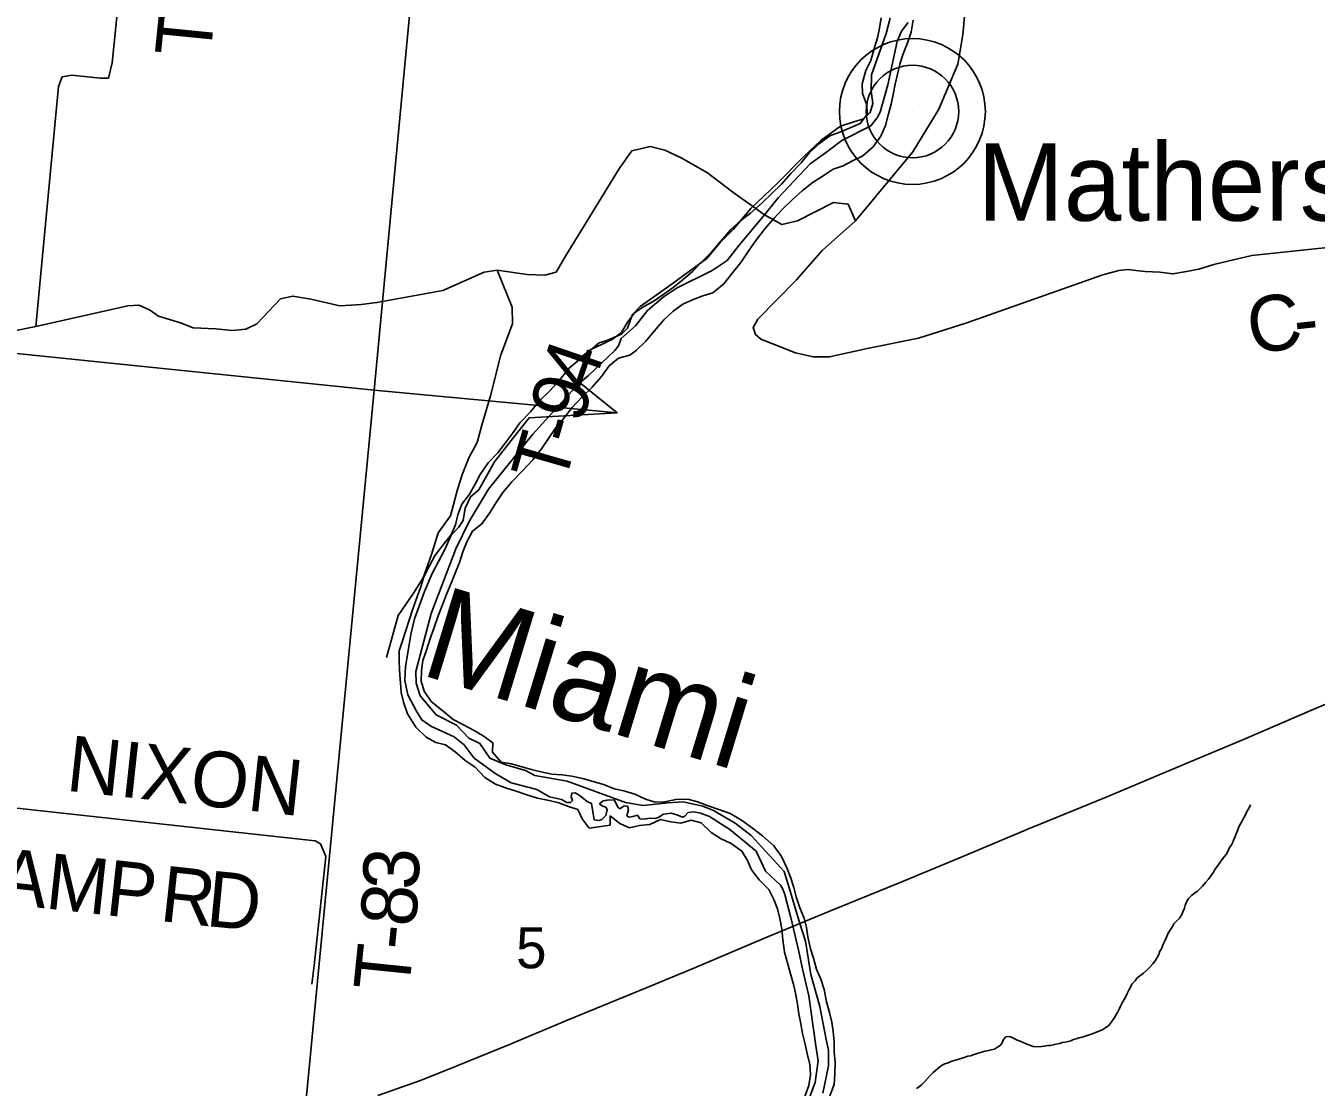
# Model space of a CAD drawing. Extents: x 1310247 to 1664935, y 284496 to 704931.
# Drawn here: x 1511194 to 1518144, y 520097 to 525811 of the extents above; entities that cross this region are included whole.
import ezdxf

# ---------------------------------------------------------------- set-up
doc = ezdxf.new("R2010")
doc.units = 0
for name, color, linetype in [('GM_X_Adjacent_County', 7, 'Continuous'), ('GM_X_Airport_Text_Class_2', 7, 'Continuous'), ('GM_X_City_Street', 7, 'Continuous'), ('GM_X_County', 7, 'Continuous'), ('GM_X_County_Road_Text', 7, 'Continuous'), ('GM_X_County_Subdivision_Text', 7, 'Continuous'), ('GM_X_Interstate_Route', 7, 'Continuous'), ('GM_X_Major_River_Text', 7, 'Continuous'), ('GM_X_Minor_River_Text', 7, 'Continuous'), ('GM_X_State_Shield', 7, 'Continuous'), ('GM_X_Township_Road', 7, 'Continuous'), ('GM_X_Township_Subdivision', 7, 'Continuous'), ('GM_X_Unincorporated', 7, 'Continuous'), ('GM_X_US_Location', 7, 'Continuous')]:
    doc.layers.add(name, color=color, linetype=linetype)

msp = doc.modelspace()

# ---------------------------------------------------------------- linework, layer by layer
at = {"layer": 'GM_X_Adjacent_County'}
for points in [[(1515946, 525828.7), (1515910.3, 525782), (1515886.8, 525726.7), (1515836, 525493.3), (1515794.6, 525347.1), (1515778.5, 525316.5), (1515745.2, 525273.1), (1515589.8, 525194.1), (1515501.2, 525128), (1515417.9, 525068.6), (1515246.2, 524884.7), (1515171.9, 524793.8), (1515035.9, 524630.1), (1514971.3, 524548.1), (1514890.2, 524493.5), (1514701.3, 524400.8), (1514626.6, 524350.3), (1514542.6, 524279.3), (1514477.8, 524196.4), (1514400.4, 524127.4), (1514386.2, 524087.4), (1514367.1, 524064), (1514225.3, 523927.9), (1514168, 523882.4), (1513923.9, 523612.8), (1513685, 523316.2), (1513582.9, 523145.5), (1513509.6, 522994.8), (1513376.8, 522647.6), (1513294.4, 522335.7), (1513295.6, 522272.3), (1513318.3, 522203), (1513403.2, 522100.9), (1513513.2, 522045.1), (1513579.1, 521976.2), (1513639.4, 521947.9), (1513692.9, 521868), (1513779.7, 521832.3), (1513884.6, 521802.3), (1513936, 521774.3), (1514109.4, 521744.6), (1514424, 521629.3), (1514519.3, 521612.5), (1514651.3, 521627.2), (1514733.5, 521632.7), (1514840.1, 521610.3), (1514898, 521586.3), (1515015.1, 521517.4), (1515101.2, 521451.2), (1515278.1, 521257.4), (1515306.8, 521164.3), (1515363.3, 520978.1), (1515392.4, 520882.2), (1515422.5, 520703.6), (1515469.9, 520531.7), (1515504.9, 520352.9), (1515517.1, 520296), (1515516.9, 520211.4), (1515486.4, 520064.8)], [(1515486.4, 520064.8), (1515516.9, 520211.4), (1515517.1, 520296), (1515504.9, 520352.9), (1515469.9, 520531.7), (1515422.5, 520703.6), (1515392.4, 520882.2), (1515363.3, 520978.1), (1515306.8, 521164.3), (1515278.1, 521257.4), (1515101.2, 521451.2), (1515015.1, 521517.4), (1514898, 521586.3), (1514840.1, 521610.3), (1514733.5, 521632.7), (1514651.3, 521627.2), (1514519.3, 521612.5), (1514424, 521629.3), (1514109.4, 521744.6), (1513936, 521774.3), (1513884.6, 521802.3), (1513779.7, 521832.3), (1513692.9, 521868), (1513639.4, 521947.9), (1513579.1, 521976.2), (1513513.2, 522045.1), (1513403.2, 522100.9), (1513318.3, 522203), (1513295.6, 522272.3), (1513294.4, 522335.7), (1513376.8, 522647.6), (1513509.6, 522994.8), (1513582.9, 523145.5), (1513685, 523316.2), (1513923.9, 523612.8), (1514168, 523882.4), (1514225.3, 523927.9), (1514367.1, 524064), (1514386.2, 524087.4), (1514400.4, 524127.4), (1514477.8, 524196.4), (1514542.6, 524279.3), (1514626.6, 524350.3), (1514701.3, 524400.8), (1514890.2, 524493.5), (1514971.3, 524548.1), (1515035.9, 524630.1), (1515171.9, 524793.8), (1515246.2, 524884.7), (1515417.9, 525068.6), (1515501.2, 525128), (1515589.8, 525194.1), (1515745.2, 525273.1), (1515778.5, 525316.5), (1515794.6, 525347.1), (1515836, 525493.3), (1515886.8, 525726.7), (1515910.3, 525782), (1515946, 525828.7)]]:
    msp.add_lwpolyline(points, dxfattribs=at)
at = {"layer": 'GM_X_City_Street'}
for points in [[(1515800.9, 525854.3), (1515792, 525798.4), (1515781.2, 525746.5), (1515764.4, 525694.6), (1515745.2, 525624.8), (1515718.4, 525571.2), (1515699.2, 525499.4), (1515700.4, 525447.3), (1515721.6, 525388.8), (1515726.8, 525336.7), (1515687.9, 525285.2), (1515633.4, 525262), (1515579, 525238.8), (1515524.6, 525219.7), (1515467.8, 525178.5), (1515414.9, 525129.2), (1515370, 525073.8), (1515315, 525016.6), (1515264, 524959.3), (1515211.1, 524908.1), (1515160.3, 524858.8), (1515097.3, 524801.7), (1515044.5, 524762.4), (1514991.7, 524715.2), (1514936.6, 524651.9), (1514887.6, 524592.6), (1514834.7, 524541.4), (1514785.8, 524490), (1514735, 524444.8), (1514680.2, 524401.6), (1514629.6, 524366.3), (1514572.9, 524327.1), (1514522.4, 524299.9), (1514471.7, 524266.6), (1514434.9, 524215.1), (1514401.9, 524159.5), (1514351.3, 524122.3), (1514294.7, 524095.1), (1514236.2, 524068), (1514179.4, 524022.8), (1514118.3, 523963.6), (1514065.3, 523900.4), (1514018.3, 523847), (1513961.4, 523791.8), (1513912.4, 523732.5), (1513855.3, 523673.3), (1513818.5, 523621.8), (1513775.5, 523564.4), (1513736.6, 523512.9), (1513683.7, 523457.7), (1513640.6, 523396.3), (1513613.7, 523342.6), (1513582.8, 523289), (1513541.9, 523235.6), (1513521, 523177.8), (1513508.1, 523124), (1513485.3, 523070.2), (1513442.3, 523016.8), (1513399.4, 522961.4), (1513370.5, 522907.8), (1513337.5, 522844.2), (1513320.6, 522790.4), (1513301.7, 522736.6), (1513278.7, 522672.9), (1513259.8, 522617.1), (1513240.8, 522555.3), (1513221.9, 522499.6), (1513205, 522445.8), (1513204.2, 522393.7), (1513207.4, 522341.6), (1513212.3, 522271.4), (1513215.6, 522221.3), (1513228.8, 522169), (1513249.9, 522106.6), (1513294.9, 522035.8), (1513350.1, 521980.9), (1513401.8, 521952.1), (1513453.7, 521939.2), (1513507.2, 521902.4), (1513560.6, 521855.5), (1513614.2, 521820.6), (1513665.4, 521763.7), (1513723, 521728.8), (1513776.8, 521707.9), (1513834.6, 521691), (1513892.4, 521670.1), (1513950.3, 521653.1), (1514012.2, 521640.2), (1514064.1, 521627.3), (1514115.9, 521608.5), (1514167.8, 521591.7), (1514191, 521541.3), (1514228.3, 521490.6), (1514290.6, 521499.7), (1514340.8, 521506.9), (1514341.6, 521556.9)], [(1514447.8, 524037.9), (1514482.6, 524064.1), (1514533.5, 524113.4), (1514578.4, 524166.8), (1514629.5, 524228.1), (1514680.3, 524275.4), (1514733, 524312.6), (1514785.4, 524335.8), (1514839.9, 524357), (1514894.3, 524374.2), (1514953.1, 524421.3), (1515000.1, 524480.7), (1515045.1, 524536.1), (1515084.1, 524595.6), (1515125.1, 524655), (1515174.1, 524718.3), (1515223.1, 524773.7), (1515270, 524825), (1515320.8, 524874.3), (1515377.7, 524925.5), (1515434.5, 524968.7), (1515489.2, 525003.9), (1515541.8, 525039.1), (1515596.2, 525058.3), (1515646.7, 525083.6), (1515701.2, 525110.8), (1515758.1, 525159.9), (1515799.1, 525217.4), (1515824, 525275.1), (1515841, 525336.9), (1515853.8, 525388.8), (1515864.7, 525440.7), (1515875.5, 525496.6), (1515888.4, 525550.5), (1515901.2, 525604.4), (1515920.1, 525660.2), (1515943.1, 525719.9), (1515962, 525777.7), (1515973, 525841.6)], [(1515524.7, 520050.7), (1515547.6, 520110.4), (1515550.5, 520166.4), (1515553.5, 520230.5), (1515548.4, 520286.6), (1515547.2, 520342.7), (1515542.1, 520396.8), (1515534.8, 520447), (1515521.6, 520499.3), (1515506.5, 520555.6), (1515493.5, 520621.9), (1515476.3, 520678.2), (1515453.1, 520732.6), (1515436, 520791), (1515420.7, 520841.3), (1515405.7, 520905.6), (1515398.4, 520955.8), (1515385.2, 521006), (1515362, 521062.5), (1515342.9, 521120.8), (1515329.6, 521171.1), (1515312.5, 521227.4), (1515293.2, 521277.8), (1515264.1, 521338.3), (1515222.9, 521397), (1515161.6, 521450.1), (1515108.1, 521491), (1515048.7, 521533.9), (1514987.1, 521570.9), (1514931.3, 521589.8), (1514869.5, 521610.8), (1514811.8, 521633.7), (1514759.8, 521646.6), (1514695.7, 521645.5), (1514635.4, 521632.5), (1514583.2, 521631.3), (1514531.4, 521648.1), (1514473.7, 521675), (1514419.8, 521689.9), (1514363.9, 521702.8), (1514306.1, 521725.7), (1514250.3, 521742.6), (1514192.4, 521759.5), (1514134.5, 521770.4), (1514080.5, 521779.3), (1514026.4, 521782.1), (1513968.5, 521795), (1513916.6, 521807.9), (1513864.7, 521820.7), (1513808.9, 521837.6), (1513754.9, 521846.4), (1513707.6, 521901.2), (1513708.4, 521951.3), (1513656.9, 521988.1), (1513605.2, 522019), (1513551.6, 522047.8), (1513495.9, 522076.8), (1513430.6, 522129.8), (1513379.1, 522170.7), (1513341.9, 522225.3), (1513322.7, 522281.7), (1513325.6, 522337.7), (1513332.5, 522393.7), (1513351.4, 522449.5), (1513370.3, 522507.3), (1513393.4, 522571), (1513414.4, 522634.8), (1513437.4, 522694.5), (1513462.3, 522754.2), (1513485.2, 522809.9), (1513506.1, 522863.6), (1513529.1, 522921.4), (1513548, 522979.1), (1513568.9, 523032.9), (1513599.8, 523090.5), (1513650.5, 523129.8), (1513691.5, 523187.2), (1513726.4, 523244.7), (1513763.3, 523298.2), (1513812.3, 523355.6), (1513869.4, 523414.8), (1513924.4, 523474), (1513971.4, 523533.3), (1514008.3, 523588.8), (1514047.3, 523644.3), (1514092.2, 523699.7), (1514137.2, 523757.1), (1514188.2, 523812.3), (1514245.1, 523865.5), (1514294.1, 523922.9), (1514335, 523980.3), (1514385.8, 524021.6), (1514447.8, 524037.9)], [(1514341.6, 521556.9), (1514393.1, 521516.1), (1514444.8, 521493.3), (1514499.1, 521506.4), (1514555.3, 521511.6), (1514611.9, 521538.7), (1514667.8, 521525.8), (1514721.8, 521519), (1514778.1, 521534.1), (1514832, 521519.3), (1514885.3, 521468.4), (1514938.9, 521433.5), (1514992.6, 521408.6), (1515050.1, 521367.7), (1515081.4, 521317.1), (1515102.7, 521266.8), (1515143.9, 521214), (1515195.2, 521161.2), (1515222.4, 521106.7), (1515241.7, 521056.3), (1515254.9, 521004.1), (1515266.1, 520949.8), (1515271.2, 520889.7), (1515280.2, 520823.4), (1515297.2, 520759.1), (1515316.2, 520694.7), (1515329.5, 520644.5), (1515340.7, 520594.2), (1515350, 520544), (1515357.2, 520491.8), (1515368.3, 520437.6), (1515377.6, 520385.4), (1515390.7, 520329.1), (1515401.9, 520278.9), (1515417, 520218.6), (1515420.2, 520162.4), (1515411.3, 520106.5), (1515390.3, 520046.8)]]:
    msp.add_lwpolyline(points, dxfattribs=at)
at = {"layer": 'GM_X_County'}
for points in [[(1509175.9, 529957.5), (1513608.2, 529561.6), (1513069.3, 523850.4), (1507676.2, 524402.8), (1508208, 530053.6)], [(1513069.3, 523850.4), (1512614.9, 519095.5), (1507180.6, 519609.2), (1507676.2, 524402.8)]]:
    msp.add_lwpolyline(points, close=True, dxfattribs=at)
for points in [[(1515849.2, 525851.7), (1515827.8, 525770.1), (1515747.9, 525547.5), (1515746.4, 525459.6), (1515755.2, 525393.4), (1515742.4, 525343.7), (1515707.8, 525310.3), (1515653.6, 525295.2), (1515581.2, 525270.5), (1515475.9, 525194.3), (1515382.4, 525106), (1515242, 524964.5), (1515099.6, 524827), (1515003.7, 524714.6), (1514934.5, 524643.9), (1514861, 524559.2), (1514662.6, 524412.6), (1514502.6, 524299.5), (1514461.9, 524256.2), (1514434.6, 524182.7), (1514402.1, 524151.2), (1514323.5, 524116.6), (1514281.3, 524105.3), (1514198.1, 524032.8), (1514100.7, 523952.5), (1514378.8, 523727.7), (1513069.3, 523850.4), (1513608.2, 529561.6)], [(1512614.9, 519095.5), (1513069.3, 523850.4), (1514378.8, 523727.7), (1513904.4, 523700), (1513808.3, 523577.7), (1513718.3, 523463.3), (1513633.8, 523312.8), (1513589.1, 523275.6), (1513560.1, 523214.1), (1513548.9, 523148.3), (1513524.3, 523110.7), (1513485.6, 523069.4), (1513450.2, 522992), (1513382, 522863.2), (1513340.4, 522766), (1513287.8, 522618.9), (1513268.5, 522543.3), (1513239.4, 522361.9), (1513236.1, 522285.9), (1513250.8, 522209.7), (1513297.2, 522120.9), (1513326.4, 522074.4), (1513375.8, 522039.6), (1513500.8, 521983.4), (1513554, 521940.5), (1513608.7, 521867.6), (1513725.2, 521783.6), (1513808.4, 521736.2), (1513945.7, 521699.8), (1514015, 521660.6), (1514078.7, 521645.5), (1514108.4, 521629), (1514128.4, 521628.6), (1514138.6, 521640.5), (1514131, 521660.6), (1514135.3, 521680.5), (1514153.3, 521682.2), (1514179, 521665.7), (1514216.5, 521635.1), (1514240.3, 521624.7), (1514254.8, 521536.5), (1514280.7, 521532), (1514296.8, 521537.7), (1514317.2, 521559.4), (1514325.7, 521589.2), (1514319.9, 521603.3), (1514298.1, 521611.7), (1514284.3, 521621.9), (1514303.9, 521638.4), (1514336.6, 521643), (1514364.6, 521642.6), (1514381.9, 521604.3), (1514393.8, 521596), (1514416, 521611.7), (1514434, 521609.3), (1514439.6, 521589.3), (1514431.1, 521557.4), (1514443, 521551.2), (1514463, 521554.9), (1514489.1, 521560.4), (1514500.8, 521542.2), (1514524.8, 521539.8), (1514554.9, 521545.3), (1514584.8, 521542.7), (1514602.9, 521550.4), (1514629.2, 521566), (1514669.3, 521571.3), (1514705.1, 521560.6), (1514730.9, 521550.2), (1514743, 521556), (1514761.3, 521575.7), (1514791.4, 521579.2), (1514827.2, 521572.5), (1514876.9, 521553.7), (1514985.7, 521483.8), (1515127.6, 521367.4), (1515177.7, 521260.6), (1515257.9, 521185.1), (1515270.9, 521162.2), (1515281.5, 521134.8), (1515313.4, 521010.3), (1515358.2, 520827.5), (1515376.5, 520733.2), (1515412, 520588.7), (1515449.4, 520320.1), (1515461.9, 520237.9), (1515445.9, 520122.2), (1515410.2, 520027.4)]]:
    msp.add_lwpolyline(points, dxfattribs=at)
at = {"layer": 'GM_X_County_Road_Text'}
for points in [[(1517821.4, 531984.3), (1517731.4, 532059.5), (1517630.5, 532163), (1517557.1, 531889.3), (1517498.1, 531653.5), (1517429.7, 531465.9), (1517014.2, 530558.9), (1516676.5, 529797.3), (1516581, 529523.8), (1516514.2, 529294.1), (1516452.8, 529026.2), (1516398.3, 528660.1), (1516268.9, 526085.5), (1516241, 525763.1), (1516213, 525605.1), (1516112, 525361.7), (1515971, 525132.8), (1515661.7, 524760.4)], [(1511247, 524193.2), (1511743.1, 524303.7), (1511801.9, 524307.3), (1511859.5, 524282.6), (1511907.7, 524248.5), (1512026.4, 524212), (1512094.6, 524185), (1512216.9, 524179.1), (1512306.2, 524170.9), (1512379.1, 524178), (1512437.9, 524207.4), (1512566.1, 524340.5), (1512632.8, 524355.8), (1512728.8, 524339.1), (1512885.9, 524304.4), (1512999.9, 524311.3), (1513084.7, 524321.1), (1513440.7, 524386.4), (1513663.2, 524485.1), (1513732.7, 524496.3), (1513894, 524472.6), (1513990, 524468.4), (1514049.8, 524485.1), (1514099.8, 524571.4), (1514391.1, 525044.6), (1514457.2, 525138.7), (1514557.3, 525160.9), (1514635.2, 525141.5), (1514724.2, 525099.7), (1514866, 525019.1), (1515002.3, 524916.2), (1515120.9, 524830.7)], [(1515120.9, 524830.7), (1515171.9, 524793.8), (1515266.5, 524741), (1515349.9, 524760.5), (1515543.2, 524860.6), (1515623.8, 524850.9), (1515661.7, 524760.4)], [(1503046.2, 524841), (1507709.5, 524409.8), (1509517.7, 524228.8), (1510413.2, 524141.6), (1510507.7, 524134.5), (1510790.2, 524118.3), (1510868.6, 524118.3), (1510962.5, 524134.5), (1511247, 524193.2)], [(1515661.7, 524760.4), (1515661.7, 524760.4), (1515482.4, 524601.4), (1515345.1, 524443.7), (1515137.2, 524232.1), (1515112.1, 524187.6), (1515124.7, 524148.6), (1515152.4, 524125), (1515340.2, 524049.9), (1515434.7, 524029), (1515522.3, 524029), (1515733.7, 524074.9), (1516002.1, 524129.2), (1516256.5, 524209.8), (1516994.9, 524469.9), (1517081.1, 524493.5), (1517131.2, 524499), (1517171.5, 524493.5), (1517222.9, 524489.3), (1517300.8, 524485.1), (1517372, 524475.7), (1517445.5, 524489.3), (1517510.8, 524501.8), (1517592.8, 524525.5), (1517667.9, 524544.9), (1517797.3, 524575.5), (1518000.3, 524596.4), (1518343.7, 524632.5)]]:
    msp.add_lwpolyline(points, dxfattribs=at)
at = {"layer": 'GM_X_County_Subdivision_Text'}
for points in [[(1511247, 524193.2), (1511369.3, 525485.1), (1511390, 525536.9), (1511441.8, 525544.7), (1511594.7, 525529.1), (1511640, 525529.1), (1511659.5, 525612), (1511820.8, 527204), (1511830.5, 527256), (1511853.8, 527283.3), (1511896.5, 527289.7), (1513276.3, 527135.6), (1513335.9, 527140.8), (1513383.8, 527162.8), (1513389, 527214.6), (1513580.5, 529383.7)], [(1513732.7, 524496.3), (1513814, 524297), (1513814.9, 524206.8), (1513752.8, 524039.1), (1513696.1, 523819.3), (1513650.1, 523661.5), (1513624.9, 523567.6), (1513581.8, 523488), (1513546.7, 523398.2), (1513519.7, 523314.3), (1513481.9, 523172.5), (1513414.7, 523081.1), (1513379.2, 522965.3), (1513333.6, 522839.5), (1513282.5, 522756), (1513199, 522636.7), (1513136.1, 522411)], [(1512734, 520652.2), (1512746.1, 520752.6), (1512810.5, 521338.7), (1512781.3, 521407.2), (1512751.5, 521423.6), (1512685.5, 521430.4), (1510275.7, 521694.1), (1510167.9, 521729.5), (1510148.5, 521777.8), (1510143.3, 521846), (1510413.2, 524141.6)]]:
    msp.add_lwpolyline(points, dxfattribs=at)
at = {"layer": 'GM_X_Major_River_Text'}
msp.add_line((1515969.2, 525349.9), (1515969.2, 525349.9), dxfattribs=at)
at = {"layer": 'GM_X_Minor_River_Text'}
for points in [[(1517109.4, 520568.6), (1517117.8, 520584.5), (1517126.2, 520600.4), (1517134.7, 520618.4), (1517141.1, 520632.3), (1517151.6, 520652.2), (1517168.1, 520670), (1517178.5, 520683.9), (1517198.9, 520699.6), (1517213.3, 520711.3), (1517231.8, 520727.1), (1517250.3, 520744.8), (1517264.7, 520760.6), (1517277.2, 520776.5), (1517287.6, 520794.4), (1517296.1, 520810.3), (1517302.5, 520828.2), (1517310.9, 520842.1), (1517315.2, 520858.1), (1517323.7, 520874.1), (1517330, 520888), (1517338.4, 520903.9), (1517344.9, 520921.9), (1517355.3, 520939.8), (1517369.9, 520961.6), (1517376.3, 520975.6), (1517394.8, 520993.3), (1517407.2, 521007.1), (1517419.7, 521027), (1517426.1, 521040.9), (1517434.6, 521060.9), (1517438.9, 521074.9), (1517445.4, 521094.8), (1517455.9, 521112.7), (1517472.3, 521128.5), (1517486.7, 521140.3), (1517505.1, 521152), (1517519.5, 521165.8), (1517531.9, 521179.6), (1517548.4, 521199.4), (1517562.9, 521217.2), (1517577.4, 521237.1), (1517589.9, 521254.9), (1517598.3, 521268.8), (1517610.7, 521284.7), (1517623.2, 521302.5), (1517635.7, 521320.4), (1517648.1, 521336.2), (1517658.5, 521350.1), (1517669, 521370), (1517675.3, 521383.9), (1517687.8, 521401.8), (1517694.2, 521415.7), (1517700.5, 521429.7), (1517706.9, 521445.6), (1517713.3, 521461.6), (1517719.7, 521477.5), (1517726.1, 521493.5), (1517732.5, 521509.5), (1517740.9, 521523.3), (1517749.3, 521537.3), (1517755.6, 521551.2), (1517764, 521567.1), (1517770.4, 521581.1), (1517780.8, 521597), (1517789.3, 521616.9)], [(1515991.4, 520088.8), (1516005.7, 520098.6), (1516020.1, 520110.4), (1516036.6, 520128.2), (1516051.1, 520144), (1516065.6, 520161.8), (1516080, 520175.6), (1516104.6, 520195.2), (1516125.1, 520213), (1516143.4, 520222.7), (1516161.7, 520228.4), (1516175.9, 520234.1), (1516194.1, 520239.8), (1516208.3, 520243.6), (1516230.6, 520251.2), (1516246.9, 520256.9), (1516267.2, 520264.6), (1516281.3, 520266.3), (1516295.5, 520270.1), (1516311.7, 520275.8), (1516327.9, 520281.6), (1516342.1, 520285.3), (1516358.3, 520291), (1516372.5, 520292.8), (1516392.7, 520298.5), (1516410.9, 520302.1), (1516427.3, 520311.9), (1516441.6, 520321.7), (1516451.9, 520335.5), (1516460.4, 520353.5), (1516472.8, 520367.3), (1516493, 520369), (1516512.9, 520360.5), (1516528.8, 520352.2), (1516548.8, 520343.8), (1516568.7, 520335.4), (1516586.7, 520329.1), (1516604.6, 520320.7), (1516618.6, 520316.4), (1516646.7, 520313.9), (1516664.9, 520315.6), (1516679, 520317.3), (1516697.2, 520321), (1516711.3, 520320.8), (1516727.5, 520324.5), (1516741.7, 520328.2), (1516763.9, 520331.8), (1516778.1, 520337.6), (1516792.2, 520339.4), (1516808.4, 520343.1), (1516822.6, 520346.8), (1516836.8, 520352.6), (1516851, 520356.4), (1516865.2, 520362.1), (1516883.4, 520365.8), (1516899.7, 520371.6), (1516915.9, 520377.3), (1516934.1, 520383), (1516954.4, 520390.6), (1516978.8, 520400.2), (1516995.1, 520408), (1517011.4, 520417.7), (1517025.7, 520427.5), (1517036.1, 520441.4), (1517046.5, 520455.2), (1517054.8, 520469.2), (1517065.3, 520485), (1517073.6, 520499), (1517080, 520512.9), (1517090.5, 520532.8), (1517099, 520550.7), (1517109.4, 520568.6)]]:
    msp.add_lwpolyline(points, dxfattribs=at)
at = {"layer": 'GM_X_State_Shield'}
for points in [[(1516598.4, 521488.7), (1516611.5, 521494.2), (1517013, 521658.2), (1517388.5, 521816.5), (1517751.9, 521968.9), (1518143.5, 522137), (1518414.5, 522248.4)], [(1514500.8, 520616.7), (1514792.4, 520738.3), (1515171.9, 520898.5), (1515363.3, 520978.1), (1515519.2, 521043.1), (1515902.7, 521199.3), (1516262.1, 521347.6), (1516581.9, 521481.8), (1516598.4, 521488.7)], [(1513090, 520051.2), (1513318.8, 520132.9), (1513521.5, 520212.9), (1513798.5, 520326.2), (1514115.8, 520459), (1514483.2, 520609.3), (1514500.8, 520616.7)]]:
    msp.add_lwpolyline(points, dxfattribs=at)
at = {"layer": 'GM_X_Unincorporated'}
for radius in [392.8, 249]:
    msp.add_circle((1515969.2, 525349.9), radius, dxfattribs=at)

# ---------------------------------------------------------------- texts
at = {"layer": 'GM_X_Airport_Text_Class_2'}
msp.add_text('Miami', height=499.99, rotation=343.03756, dxfattribs=at).set_placement((1513307.4, 522321.7))
at = {"layer": 'GM_X_Interstate_Route'}
msp.add_text('Mathers Mills', height=417, rotation=0.00001, dxfattribs=at).set_placement((1516320.1, 524761.9))
at = {"layer": 'GM_X_Township_Road'}
for s, rotation, p in [('C', 8.40995, (1517795.1, 524041.8)), ('-', 6.17038, (1518035.8, 524077.5))]:
    msp.add_text(s, height=300, rotation=rotation, dxfattribs=at).set_placement(p)
at = {"layer": 'GM_X_Township_Subdivision'}
for s, rotation, p in [('T-83', 84.32502, (1512187.5, 525634.6)), ('4', 71.11248, (1514240.8, 523836.6)), ('9', 73.29327, (1514188.6, 523662.4)), ('-', 73.84657, (1514154.5, 523544.8)), ('T', 73.97807, (1514092.7, 523329.3)), ('NIXON', 353.77816, (1511404.9, 521693.9)), ('A', 353.73302, (1511030.2, 521088.7)), ('M', 353.73189, (1511292.6, 521059.9)), ('P', 353.735, (1511616.3, 521024.3)), ('3', 88.26524, (1513308.8, 521157)), ('R', 353.79446, (1511909.7, 520992.2)), ('D', 354.4544, (1512158.4, 520965.1)), ('8', 85.14809, (1513292.2, 520955.1)), ('-', 84.33078, (1513279.6, 520827.9)), ('T', 84.12692, (1513256.5, 520603.5))]:
    msp.add_text(s, height=300, rotation=rotation, dxfattribs=at).set_placement(p)
at = {"layer": 'GM_X_US_Location'}
msp.add_text('5', height=221, rotation=0.00001, dxfattribs=at).set_placement((1513834.2, 520737))

doc.saveas('drawing.dxf')
